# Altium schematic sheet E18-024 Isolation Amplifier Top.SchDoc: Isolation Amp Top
size A; Author: MC; DrawnBy: M. Carlson; Organization: University of British Columbia; Address1: Physics & Astronomy Department; Address2: Electronics Lab - Room 254; Address3: 6224 Agricultural Road; Address4: Vancouver BC V6T 1Z1 Canada; DocumentNumber: E18-024; Revision: 1; SheetNumber: 1; SheetTotal: 3
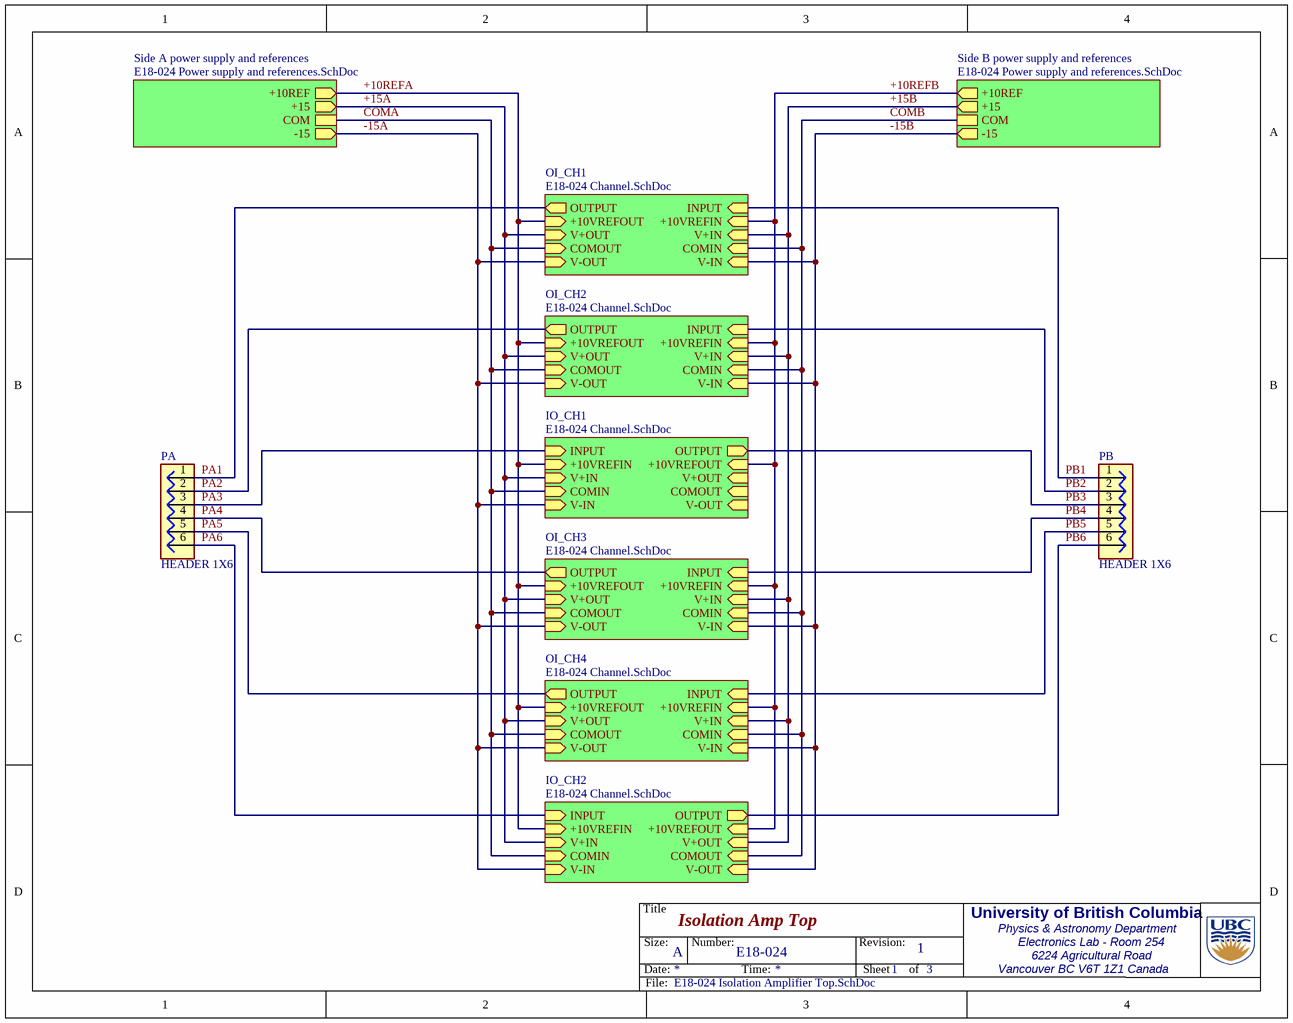
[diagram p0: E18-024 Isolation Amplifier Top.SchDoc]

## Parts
PA  HEADER 1X6  [HDR1X6 SMD]
PB  HEADER 1X6  [HDR1X6 SMD]

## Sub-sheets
IO_CH1 = E18-024 Channel.SchDoc: +10VREFIN (in), INPUT (in), +10VREFOUT (in), OUTPUT (out), V+IN (in), V-IN (in), COMIN (in), V+OUT (in), V-OUT (in), COMOUT (in)
IO_CH2 = E18-024 Channel.SchDoc: +10VREFIN (in), INPUT (in), +10VREFOUT (in), OUTPUT (out), V+IN (in), V-IN (in), COMIN (in), V+OUT (in), V-OUT (in), COMOUT (in)
OI_CH1 = E18-024 Channel.SchDoc: +10VREFIN (in), INPUT (in), +10VREFOUT (in), OUTPUT (out), V+IN (in), V-IN (in), COMIN (in), V+OUT (in), V-OUT (in), COMOUT (in)
OI_CH2 = E18-024 Channel.SchDoc: +10VREFIN (in), INPUT (in), +10VREFOUT (in), OUTPUT (out), V+IN (in), V-IN (in), COMIN (in), V+OUT (in), V-OUT (in), COMOUT (in)
OI_CH3 = E18-024 Channel.SchDoc: +10VREFIN (in), INPUT (in), +10VREFOUT (in), OUTPUT (out), V+IN (in), V-IN (in), COMIN (in), V+OUT (in), V-OUT (in), COMOUT (in)
OI_CH4 = E18-024 Channel.SchDoc: +10VREFIN (in), INPUT (in), +10VREFOUT (in), OUTPUT (out), V+IN (in), V-IN (in), COMIN (in), V+OUT (in), V-OUT (in), COMOUT (in)
Side A power supply and references = E18-024 Power supply and references.SchDoc: +15 (out), COM, -15 (out), +10REF (out)
Side B power supply and references = E18-024 Power supply and references.SchDoc: +15 (out), COM, -15 (out), +10REF (out)

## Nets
+10REFA: sheet Side A power supply and references/+10REF, sheet IO_CH1/+10VREFIN, sheet IO_CH2/+10VREFIN, sheet OI_CH1/+10VREFOUT, sheet OI_CH2/+10VREFOUT, sheet OI_CH3/+10VREFOUT, sheet OI_CH4/+10VREFOUT
+10REFB: sheet Side B power supply and references/+10REF, sheet IO_CH1/+10VREFOUT, sheet IO_CH2/+10VREFOUT, sheet OI_CH1/+10VREFIN, sheet OI_CH2/+10VREFIN, sheet OI_CH3/+10VREFIN, sheet OI_CH4/+10VREFIN
+15A: sheet Side A power supply and references/+15, sheet IO_CH1/V+IN, sheet IO_CH2/V+IN, sheet OI_CH1/V+OUT, sheet OI_CH2/V+OUT, sheet OI_CH3/V+OUT, sheet OI_CH4/V+OUT
+15B: sheet Side B power supply and references/+15, sheet IO_CH2/V+OUT, sheet OI_CH1/V+IN, sheet OI_CH2/V+IN, sheet OI_CH3/V+IN, sheet OI_CH4/V+IN
-15A: sheet Side A power supply and references/-15, sheet IO_CH1/V-IN, sheet IO_CH2/V-IN, sheet OI_CH1/V-OUT, sheet OI_CH2/V-OUT, sheet OI_CH3/V-OUT, sheet OI_CH4/V-OUT
-15B: sheet Side B power supply and references/-15, sheet IO_CH2/V-OUT, sheet OI_CH1/V-IN, sheet OI_CH2/V-IN, sheet OI_CH3/V-IN, sheet OI_CH4/V-IN
COMA: sheet Side A power supply and references/COM, sheet IO_CH1/COMIN, sheet IO_CH2/COMIN, sheet OI_CH1/COMOUT, sheet OI_CH2/COMOUT, sheet OI_CH3/COMOUT, sheet OI_CH4/COMOUT
COMB: sheet Side B power supply and references/COM, sheet IO_CH2/COMOUT, sheet OI_CH1/COMIN, sheet OI_CH2/COMIN, sheet OI_CH3/COMIN, sheet OI_CH4/COMIN
PA1: PA.1 ; sheet OI_CH1/OUTPUT
PA2: PA.2 ; sheet OI_CH2/OUTPUT
PA3: PA.3 ; sheet IO_CH1/INPUT
PA4: PA.4 ; sheet OI_CH3/OUTPUT
PA5: PA.5 ; sheet OI_CH4/OUTPUT
PA6: PA.6 ; sheet IO_CH2/INPUT
PB1: PB.1 ; sheet OI_CH1/INPUT
PB2: PB.2 ; sheet OI_CH2/INPUT
PB3: PB.3 ; sheet IO_CH1/OUTPUT
PB4: PB.4 ; sheet OI_CH3/INPUT
PB5: PB.5 ; sheet OI_CH4/INPUT
PB6: PB.6 ; sheet IO_CH2/OUTPUT

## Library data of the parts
PA PB = HEADER 1X6: 0.1" Spacing 1x6 Header; Manufacturer: AMP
